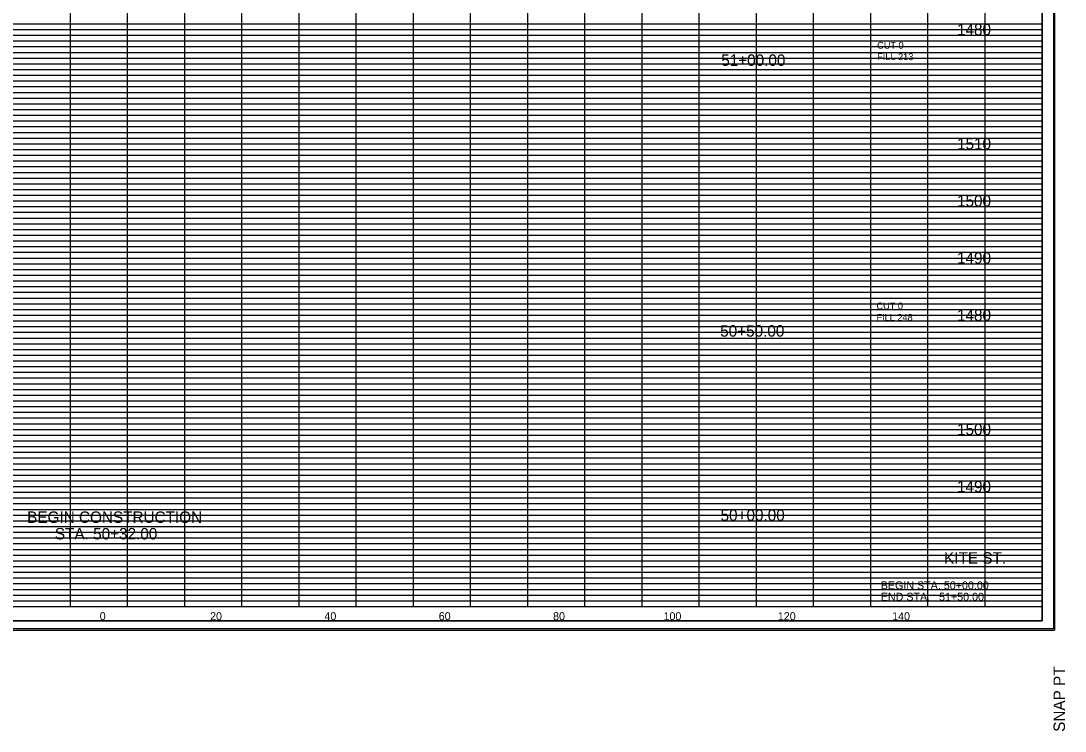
# Model space of a CAD drawing. Extents: x 980 to 1324, y 978 to 1497.
# Drawn here: x 1141.3 to 1324, y 978.2 to 1102.5 of the extents above; entities that cross this region are included whole.
import ezdxf

# ---------------------------------------------------------------- set-up
doc = ezdxf.new("R2010")
doc.units = 0
for name, color, linetype in [('DESIGN - SHEET - Corner Text', 7, 'Continuous'), ('DESIGN - SHEET - Light Grid', 7, 'Continuous'), ('DESIGN - SHEET - Linework', 7, 'Continuous'), ('DESIGN - SHEET - Plot Shape', 7, 'Continuous'), ('DESIGN - TYPICAL - Text', 7, 'Continuous')]:
    doc.layers.add(name, color=color, linetype=linetype)

# ---------------------------------------------------------------- blocks, each defined once
blk = doc.blocks.new('XSTSHT')
at = {"layer": 'DESIGN - SHEET - Light Grid'}
for p, q in [((8, 10.2), (16, 10.2)), ((8, 10.1), (16, 10.1)), ((16, 10.2), (24, 10.2)), ((16, 10.1), (24, 10.1)), ((24, 10.2), (32, 10.2)), ((24, 10.1), (32, 10.1)), ((8, 9.9), (16, 9.9)), ((16, 9.9), (24, 9.9)), ((24, 9.9), (32, 9.9)), ((8, 9.8), (16, 9.8)), ((8, 9.7), (16, 9.7)), ((16, 9.8), (24, 9.8)), ((16, 9.7), (24, 9.7)), ((24, 9.8), (32, 9.8)), ((24, 9.7), (32, 9.7)), ((8, 9.6), (16, 9.6)), ((8, 9.5), (16, 9.5)), ((16, 9.6), (24, 9.6)), ((16, 9.5), (24, 9.5)), ((24, 9.6), (32, 9.6)), ((24, 9.5), (32, 9.5)), ((8, 9.4), (16, 9.4)), ((16, 9.4), (24, 9.4)), ((24, 9.4), (32, 9.4)), ((8, 9.3), (16, 9.3)), ((8, 9.2), (16, 9.2)), ((16, 9.3), (24, 9.3)), ((16, 9.2), (24, 9.2)), ((24, 9.3), (32, 9.3)), ((24, 9.2), (32, 9.2)), ((8, 9.1), (16, 9.1)), ((16, 9.1), (24, 9.1)), ((24, 9.1), (32, 9.1)), ((8, 8.9), (16, 8.9)), ((8, 8.8), (16, 8.8)), ((16, 8.9), (24, 8.9)), ((16, 8.8), (24, 8.8)), ((24, 8.9), (32, 8.9)), ((24, 8.8), (32, 8.8)), ((8, 8.7), (16, 8.7)), ((8, 8.6), (16, 8.6)), ((16, 8.7), (24, 8.7)), ((16, 8.6), (24, 8.6)), ((24, 8.7), (32, 8.7)), ((24, 8.6), (32, 8.6)), ((8, 8.5), (16, 8.5)), ((16, 8.5), (24, 8.5)), ((24, 8.5), (32, 8.5)), ((8, 8.4), (16, 8.4)), ((8, 8.3), (16, 8.3)), ((16, 8.4), (24, 8.4)), ((16, 8.3), (24, 8.3)), ((24, 8.4), (32, 8.4)), ((24, 8.3), (32, 8.3)), ((8, 8.2), (16, 8.2)), ((8, 8.1), (16, 8.1)), ((16, 8.2), (24, 8.2)), ((16, 8.1), (24, 8.1)), ((24, 8.2), (32, 8.2)), ((24, 8.1), (32, 8.1)), ((8, 7.9), (16, 7.9)), ((16, 7.9), (24, 7.9)), ((24, 7.9), (32, 7.9)), ((8, 7.8), (16, 7.8)), ((8, 7.7), (16, 7.7)), ((16, 7.8), (24, 7.8)), ((16, 7.7), (24, 7.7)), ((24, 7.8), (32, 7.8)), ((24, 7.7), (32, 7.7)), ((8, 7.6), (16, 7.6)), ((8, 7.5), (16, 7.5)), ((16, 7.6), (24, 7.6)), ((16, 7.5), (24, 7.5)), ((24, 7.6), (32, 7.6)), ((24, 7.5), (32, 7.5)), ((8, 7.4), (16, 7.4)), ((16, 7.4), (24, 7.4)), ((24, 7.4), (32, 7.4)), ((8, 7.3), (16, 7.3)), ((8, 7.2), (16, 7.2)), ((16, 7.3), (24, 7.3)), ((16, 7.2), (24, 7.2)), ((24, 7.3), (32, 7.3)), ((24, 7.2), (32, 7.2)), ((8, 7.1), (16, 7.1)), ((16, 7.1), (24, 7.1)), ((24, 7.1), (32, 7.1)), ((8, 6.9), (16, 6.9)), ((8, 6.8), (16, 6.8)), ((16, 6.9), (24, 6.9)), ((16, 6.8), (24, 6.8)), ((24, 6.9), (32, 6.9)), ((24, 6.8), (32, 6.8)), ((8, 6.7), (16, 6.7)), ((8, 6.6), (16, 6.6)), ((16, 6.7), (24, 6.7)), ((16, 6.6), (24, 6.6)), ((24, 6.7), (32, 6.7)), ((24, 6.6), (32, 6.6)), ((8, 6.5), (16, 6.5)), ((8, 6.4), (16, 6.4)), ((16, 6.5), (24, 6.5)), ((16, 6.4), (24, 6.4)), ((24, 6.5), (32, 6.5)), ((24, 6.4), (32, 6.4)), ((8, 6.3), (16, 6.3)), ((16, 6.3), (24, 6.3)), ((24, 6.3), (32, 6.3)), ((8, 6.2), (16, 6.2)), ((8, 6.1), (16, 6.1)), ((16, 6.2), (24, 6.2)), ((16, 6.1), (24, 6.1)), ((24, 6.2), (32, 6.2)), ((24, 6.1), (32, 6.1)), ((8, 5.9), (16, 5.9)), ((16, 5.9), (24, 5.9)), ((24, 5.9), (32, 5.9)), ((8, 5.8), (16, 5.8)), ((8, 5.7), (16, 5.7)), ((16, 5.8), (24, 5.8)), ((16, 5.7), (24, 5.7)), ((24, 5.8), (32, 5.8)), ((24, 5.7), (32, 5.7)), ((8, 5.6), (16, 5.6)), ((8, 5.5), (16, 5.5)), ((16, 5.6), (24, 5.6)), ((16, 5.5), (24, 5.5)), ((24, 5.6), (32, 5.6)), ((24, 5.5), (32, 5.5)), ((8, 5.4), (16, 5.4)), ((8, 5.3), (16, 5.3)), ((16, 5.4), (24, 5.4)), ((16, 5.3), (24, 5.3)), ((24, 5.4), (32, 5.4)), ((24, 5.3), (32, 5.3)), ((8, 5.2), (16, 5.2)), ((16, 5.2), (24, 5.2)), ((24, 5.2), (32, 5.2)), ((8, 5.1), (16, 5.1)), ((16, 5.1), (24, 5.1)), ((24, 5.1), (32, 5.1)), ((8, 4.9), (16, 4.9)), ((8, 4.8), (16, 4.8)), ((16, 4.9), (24, 4.9)), ((16, 4.8), (24, 4.8)), ((24, 4.9), (32, 4.9)), ((24, 4.8), (32, 4.8)), ((8, 4.7), (16, 4.7)), ((8, 4.6), (16, 4.6)), ((16, 4.7), (24, 4.7)), ((16, 4.6), (24, 4.6)), ((24, 4.7), (32, 4.7)), ((24, 4.6), (32, 4.6)), ((8, 4.5), (16, 4.5)), ((8, 4.4), (16, 4.4)), ((16, 4.5), (24, 4.5)), ((16, 4.4), (24, 4.4)), ((24, 4.5), (32, 4.5)), ((24, 4.4), (32, 4.4)), ((8, 4.3), (16, 4.3)), ((16, 4.3), (24, 4.3)), ((24, 4.3), (32, 4.3)), ((8, 4.2), (16, 4.2)), ((8, 4.1), (16, 4.1)), ((16, 4.2), (24, 4.2)), ((16, 4.1), (24, 4.1)), ((24, 4.2), (32, 4.2)), ((24, 4.1), (32, 4.1)), ((8, 3.9), (16, 3.9)), ((16, 3.9), (24, 3.9)), ((24, 3.9), (32, 3.9)), ((8, 3.8), (16, 3.8)), ((8, 3.7), (16, 3.7)), ((16, 3.8), (24, 3.8)), ((16, 3.7), (24, 3.7)), ((24, 3.8), (32, 3.8)), ((24, 3.7), (32, 3.7)), ((8, 3.6), (16, 3.6)), ((8, 3.5), (16, 3.5)), ((16, 3.6), (24, 3.6)), ((16, 3.5), (24, 3.5)), ((24, 3.6), (32, 3.6)), ((24, 3.5), (32, 3.5)), ((8, 3.4), (16, 3.4)), ((8, 3.3), (16, 3.3)), ((16, 3.4), (24, 3.4)), ((16, 3.3), (24, 3.3)), ((24, 3.4), (32, 3.4)), ((24, 3.3), (32, 3.3)), ((8, 3.2), (16, 3.2)), ((16, 3.2), (24, 3.2)), ((24, 3.2), (32, 3.2)), ((8, 3.1), (16, 3.1)), ((16, 3.1), (24, 3.1)), ((24, 3.1), (32, 3.1)), ((8, 2.9), (16, 2.9)), ((8, 2.8), (16, 2.8)), ((16, 2.9), (24, 2.9)), ((16, 2.8), (24, 2.8)), ((24, 2.9), (32, 2.9)), ((24, 2.8), (32, 2.8)), ((8, 2.7), (16, 2.7)), ((8, 2.6), (16, 2.6)), ((16, 2.7), (24, 2.7)), ((16, 2.6), (24, 2.6)), ((24, 2.7), (32, 2.7)), ((24, 2.6), (32, 2.6)), ((8, 2.5), (16, 2.5)), ((8, 2.4), (16, 2.4)), ((16, 2.5), (24, 2.5)), ((16, 2.4), (24, 2.4)), ((24, 2.5), (32, 2.5)), ((24, 2.4), (32, 2.4)), ((8, 2.3), (16, 2.3)), ((8, 2.2), (16, 2.2)), ((16, 2.3), (24, 2.3)), ((16, 2.2), (24, 2.2)), ((24, 2.3), (32, 2.3)), ((24, 2.2), (32, 2.2)), ((8, 2.1), (16, 2.1)), ((16, 2.1), (24, 2.1)), ((24, 2.1), (32, 2.1)), ((8, 1.9), (16, 1.9)), ((16, 1.9), (24, 1.9)), ((24, 1.9), (32, 1.9)), ((8, 1.8), (16, 1.8)), ((8, 1.7), (16, 1.7)), ((16, 1.8), (24, 1.8)), ((16, 1.7), (24, 1.7)), ((24, 1.8), (32, 1.8)), ((24, 1.7), (32, 1.7)), ((8, 1.6), (16, 1.6)), ((8, 1.5), (16, 1.5)), ((16, 1.6), (24, 1.6)), ((16, 1.5), (24, 1.5)), ((24, 1.6), (32, 1.6)), ((24, 1.5), (32, 1.5)), ((8, 1.4), (16, 1.4)), ((8, 1.3), (16, 1.3)), ((16, 1.4), (24, 1.4)), ((16, 1.3), (24, 1.3)), ((24, 1.4), (32, 1.4)), ((24, 1.3), (32, 1.3)), ((8, 1.2), (16, 1.2)), ((8, 1.1), (16, 1.1)), ((16, 1.2), (24, 1.2)), ((16, 1.1), (24, 1.1)), ((24, 1.2), (32, 1.2)), ((24, 1.1), (32, 1.1)), ((8, 0.9), (16, 0.9)), ((8, 0.8), (16, 0.8)), ((16, 0.9), (24, 0.9)), ((16, 0.8), (24, 0.8)), ((24, 0.9), (32, 0.9)), ((24, 0.8), (32, 0.8)), ((8, 0.7), (16, 0.7)), ((8, 0.6), (16, 0.6)), ((16, 0.7), (24, 0.7)), ((16, 0.6), (24, 0.6)), ((24, 0.7), (32, 0.7)), ((24, 0.6), (32, 0.6)), ((8, 0.5), (16, 0.5)), ((8, 0.4), (16, 0.4)), ((16, 0.5), (24, 0.5)), ((16, 0.4), (24, 0.4)), ((24, 0.5), (32, 0.5)), ((24, 0.4), (32, 0.4)), ((8, 0.3), (16, 0.3)), ((8, 0.2), (16, 0.2)), ((16, 0.3), (24, 0.3)), ((16, 0.2), (24, 0.2)), ((24, 0.3), (32, 0.3)), ((24, 0.2), (32, 0.2)), ((8, 0.1), (16, 0.1)), ((16, 0.1), (24, 0.1)), ((24, 0.1), (32, 0.1))]:
    blk.add_line(p, q, dxfattribs=at)
at = {"layer": 'DESIGN - SHEET - Linework'}
for p, q in [((32.217, 21.414), (32.217, -0.414)), ((15, 0), (15, 21)), ((16, 0), (16, 21)), ((17, 0), (17, 21)), ((18, 0), (18, 21)), ((19, 0), (19, 21)), ((20, 0), (20, 21)), ((21, 0), (21, 21)), ((22, 0), (22, 21)), ((23, 0), (23, 21)), ((24, 0), (24, 21)), ((25, 0), (25, 21)), ((26, 0), (26, 21)), ((27, 0), (27, 21)), ((28, 0), (28, 20)), ((29, 0), (29, 20)), ((30, 0), (30, 20)), ((31, 0), (31, 20)), ((0, 10), (32, 10)), ((0, 9), (32, 9)), ((0, 8), (32, 8)), ((0, 7), (32, 7)), ((0, 6), (32, 6)), ((0, 5), (32, 5)), ((0, 4), (32, 4)), ((0, 3), (32, 3)), ((0, 2), (32, 2)), ((0, 1), (32, 1)), ((-1.823, -0.414), (32.217, -0.414))]:
    blk.add_line(p, q, dxfattribs=at)
blk.add_lwpolyline([(0, 21), (0, 0), (32, 0), (32, 21), (0, 21)], dxfattribs=at)
at = {"layer": 'DESIGN - SHEET - Plot Shape'}
for points in [[(-1.803, 21.394), (32.197, 21.394), (32.197, -0.394), (-1.803, -0.394)], [(-0.85, 21), (32, 21), (32, -0.25), (-0.85, -0.25)]]:
    blk.add_lwpolyline(points, close=True, dxfattribs=at)
at = {"layer": 'DESIGN - SHEET - Corner Text'}
blk.add_text('SNAP PT  ', height=0.2, rotation=90, dxfattribs=at).set_placement((32.397, -2.194))

msp = doc.modelspace()

# ---------------------------------------------------------------- linework, layer by layer
at = {"layer": 'DESIGN - SHEET - Plot Shape'}
msp.add_lwpolyline([(991.5, 997.5), (1320, 997.5), (1320, 1210), (991.5, 1210)], close=True, dxfattribs=at)

# ---------------------------------------------------------------- block references
at = {"layer": 'DESIGN - TYPICAL - Text', "xscale": 10, "yscale": 10}
msp.add_blockref('XSTSHT', (1000, 1000), dxfattribs=at)

# ---------------------------------------------------------------- texts
at = {"layer": 'DESIGN - SHEET - Corner Text'}
for s, height, p in [('KITE ST.', 2, (1302.83, 1007.5)), ('BEGIN STA. 50+00.00', 1.4, (1291.75, 1003)), ('END STA.   51+50.00', 1.4, (1291.75, 1001))]:
    msp.add_text(s, height=height, dxfattribs=at).set_placement(p)
at = {"layer": 'DESIGN - TYPICAL - Text'}
for s, height, p in [('     1480     ', 2, (1301.37, 1100)), ('CUT 0', 1.2, (1291.12, 1097.64)), ('     51+00.00     ', 2, (1260.12, 1094.64)), ('FILL 213', 1.2, (1291.12, 1095.64)), ('     1510     ', 2, (1301.37, 1080)), ('     1500     ', 2, (1301.37, 1070)), ('     1490     ', 2, (1301.37, 1060)), ('CUT 0', 1.2, (1291, 1052.01)), ('FILL 248', 1.2, (1291, 1050.01)), ('     1480     ', 2, (1301.37, 1050)), ('     50+50.00     ', 2, (1259.94, 1047.24)), ('     1500     ', 2, (1301.37, 1030)), ('     1490     ', 2, (1301.37, 1020)), ('BEGIN CONSTRUCTION', 2, (1142.42, 1014.64)), ('     50+00.00     ', 2, (1260, 1014.99)), ('STA. 50+32.00', 2, (1147.27, 1011.74)), ('     0     ', 1.4, (1152.51, 997.6)), ('     0     ', 1.4, (1152.51, 997.6)), ('     20     ', 1.4, (1171.82, 997.6)), ('     40     ', 1.4, (1191.82, 997.6)), ('     60     ', 1.4, (1211.82, 997.6)), ('     80     ', 1.4, (1231.82, 997.6)), ('     100     ', 1.4, (1251.14, 997.6)), ('     120     ', 1.4, (1271.14, 997.6)), ('     140     ', 1.4, (1291.14, 997.6))]:
    msp.add_text(s, height=height, dxfattribs=at).set_placement(p)

doc.saveas('drawing.dxf')
